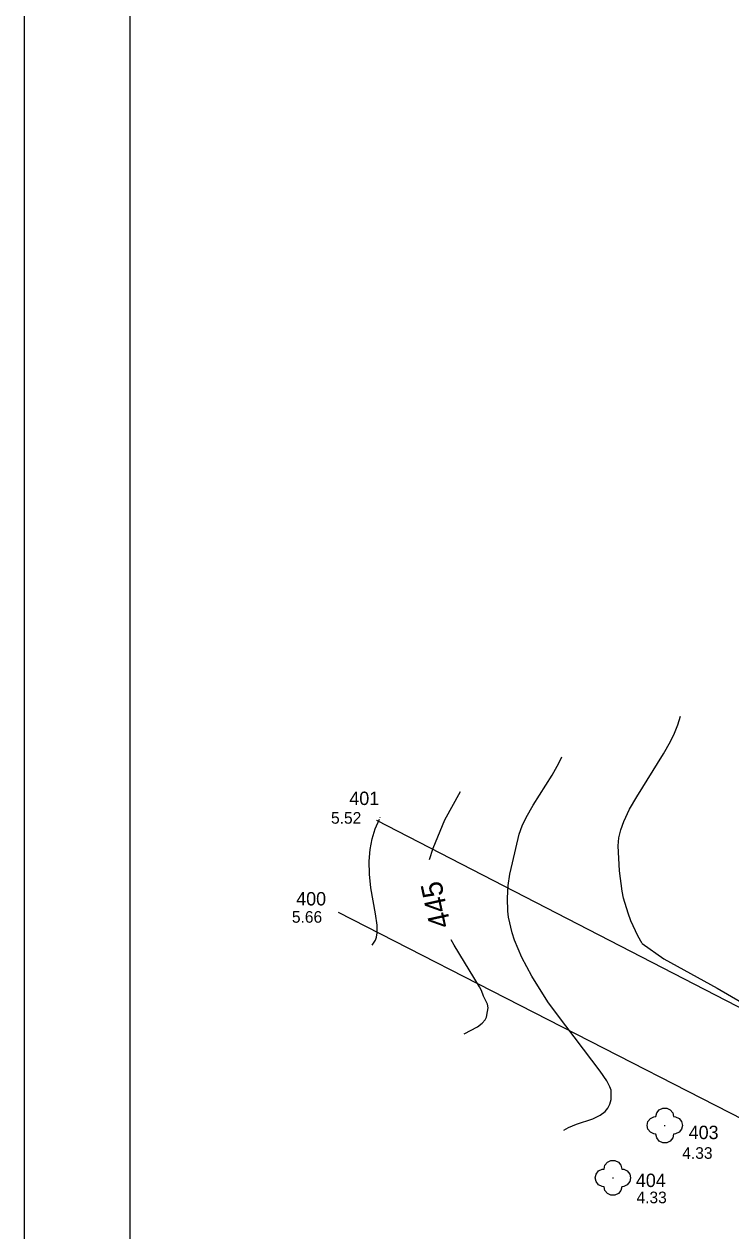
# Model space of a CAD drawing. Extents: x -792549 to -792339, y -1111914 to -1111617.
# Drawn here: x -792548.56 to -792528.5, y -1111704.34 to -1111670.1 of the extents above; entities that cross this region are included whole.
import ezdxf

# ---------------------------------------------------------------- set-up
doc = ezdxf.new("R2010")
doc.units = 0
for name, color, linetype in [('Vrstva 1', 7, 'Continuous'), ('Vrstva 24', 7, 'Continuous'), ('Vrstva 31', 7, 'Continuous'), ('Vrstva 32', 7, 'Continuous'), ('Vrstva 33', 7, 'Continuous'), ('Vrstva 44', 7, 'Continuous'), ('Vrstva 47', 7, 'Continuous'), ('Vrstva 48', 7, 'Continuous'), ('Vrstva 49', 7, 'Continuous'), ('Vrstva 50', 7, 'Continuous'), ('Vrstva 60', 7, 'Continuous')]:
    doc.layers.add(name, color=color, linetype=linetype)

# ---------------------------------------------------------------- blocks, each defined once
blk = doc.blocks.new('SC6231')
at = {"layer": 'Vrstva 1'}
blk.add_line((0, 0), (0, 0), dxfattribs=at)
blk = doc.blocks.new('3$1300')
at = {"layer": 'Vrstva 1'}
for points in [[(20, 0), (19, -4.3), (16.2, -7.8), (12.2, -9.7), (10, -10), (9, -14.3), (6.2, -17.8), (2.2, -19.7), (-2.3, -19.7), (-6.3, -17.8), (-9.1, -14.3), (-10.1, -10), (-12.3, -9.7), (-16.3, -7.8), (-19.1, -4.3), (-20.1, 0), (-19.1, 4.3), (-16.3, 7.8), (-12.3, 9.7), (-10.1, 10), (-9.1, 14.3), (-6.3, 17.8), (-2.3, 19.7), (2.2, 19.7), (6.2, 17.8), (9, 14.3), (10, 10), (12.2, 9.7), (16.2, 7.8), (19, 4.3), (20, 0)], [(-0.5, 0), (0, 0), (0.5, 0)]]:
    blk.add_lwpolyline(points, dxfattribs=at)

msp = doc.modelspace()

# ---------------------------------------------------------------- linework, layer by layer
at = {"layer": 'Vrstva 24'}
msp.add_lwpolyline([(-792545.564, -1111620.164), (-792545.564, -1111911.164), (-792341.564, -1111911.164), (-792341.564, -1111620.164)], close=True, dxfattribs=at)
at = {"layer": 'Vrstva 31'}
for points in [[(-792537.054, -1111693.81), (-792536.956, -1111693.489), (-792536.619, -1111692.678), (-792536.174, -1111691.875)], [(-792535.584, -1111697.527), (-792535.641, -1111697.417), (-792536.356, -1111696.239), (-792536.44, -1111696.085)], [(-792535.436, -1111698.281), (-792535.408, -1111698.115), (-792535.391, -1111698.015), (-792535.414, -1111697.915), (-792535.47, -1111697.8), (-792535.526, -1111697.684), (-792535.584, -1111697.527)], [(-792536.078, -1111698.754), (-792535.696, -1111698.556), (-792535.559, -1111698.452), (-792535.478, -1111698.357), (-792535.436, -1111698.281)]]:
    msp.add_lwpolyline(points, dxfattribs=at)
at = {"layer": 'Vrstva 32'}
for points in [[(-792531.018, -1111696.194), (-792531.146, -1111695.973), (-792531.343, -1111695.543), (-792531.423, -1111695.333), (-792531.547, -1111694.902), (-792531.59, -1111694.704), (-792531.667, -1111694.129), (-792531.704, -1111693.421), (-792531.686, -1111693.195), (-792531.631, -1111692.964), (-792531.544, -1111692.728), (-792531.377, -1111692.38), (-792531.175, -1111692.031), (-792530.412, -1111690.809), (-792530.219, -1111690.46), (-792530.103, -1111690.221), (-792530.006, -1111689.985), (-792529.931, -1111689.743)], [(-792531.018, -1111696.194), (-792530.405, -1111696.621), (-792528.894, -1111697.453), (-792527.31, -1111698.376), (-792527.094, -1111698.351), (-792526.964, -1111698.246)]]:
    msp.add_lwpolyline(points, dxfattribs=at)
at = {"layer": 'Vrstva 33'}
for points in [[(-792533.246, -1111701.491), (-792533.116, -1111701.408), (-792532.89, -1111701.318), (-792532.421, -1111701.163), (-792532.213, -1111701.061), (-792532.076, -1111700.958), (-792531.994, -1111700.863), (-792531.935, -1111700.752), (-792531.899, -1111700.617), (-792531.897, -1111700.388), (-792531.904, -1111700.347), (-792531.938, -1111700.258), (-792532.026, -1111700.089), (-792532.213, -1111699.812), (-792533.429, -1111698.216), (-792533.698, -1111697.844), (-792534.154, -1111697.114), (-792534.441, -1111696.588), (-792534.641, -1111696.098), (-792534.716, -1111695.883), (-792534.811, -1111695.44), (-792534.839, -1111695.27), (-792534.848, -1111694.899), (-792534.822, -1111694.541), (-792534.774, -1111694.221), (-792534.705, -1111693.898), (-792534.511, -1111693.089), (-792534.432, -1111692.854), (-792534.318, -1111692.614), (-792534.114, -1111692.262), (-792533.574, -1111691.414), (-792533.384, -1111691.069), (-792533.301, -1111690.894)], [(-792538.685, -1111696.233), (-792538.59, -1111696.092), (-792538.56, -1111696.008), (-792538.541, -1111695.883), (-792538.547, -1111695.67), (-792538.592, -1111695.348), (-792538.719, -1111694.606), (-792538.76, -1111694.221), (-792538.768, -1111693.855), (-792538.743, -1111693.525), (-792538.685, -1111693.219), (-792538.599, -1111692.94), (-792538.476, -1111692.661)], [(-792538.46, -1111692.624), (-792538.455, -1111692.614)]]:
    msp.add_lwpolyline(points, dxfattribs=at)
at = {"layer": 'Vrstva 47'}
for p, q in [((-792538.56, -1111692.69), (-792525.74, -1111699.3)), ((-792527.11, -1111701.73), (-792539.64, -1111695.31))]:
    msp.add_line(p, q, dxfattribs=at)
at = {"layer": 'Vrstva 60'}
msp.add_lwpolyline([(-792548.564, -1111617.164), (-792548.564, -1111914.164), (-792338.564, -1111914.164), (-792338.564, -1111617.164), (-792548.564, -1111617.164)], dxfattribs=at)

# ---------------------------------------------------------------- block references
at = {"layer": 'Vrstva 44', "xscale": 0.025, "yscale": 0.025000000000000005}
for p in [(-792530.38, -1111701.35), (-792531.85, -1111702.84)]:
    msp.add_blockref('3$1300', p, dxfattribs=at)
at = {"layer": 'Vrstva 48', "xscale": 0.1, "yscale": 0.10000000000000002}
for p in [(-792538.56, -1111692.69), (-792539.64, -1111695.31), (-792530.38, -1111701.35), (-792531.85, -1111702.84)]:
    msp.add_blockref('SC6231', p, dxfattribs=at)

# ---------------------------------------------------------------- texts
at = {"layer": 'Vrstva 31'}
msp.add_text('445', height=0.6, rotation=102.3983, dxfattribs=at).set_placement((-792536.448, -1111695.688))
at = {"layer": 'Vrstva 49'}
for s, p in [('401', (-792539.333, -1111692.26)), ('400', (-792540.841, -1111695.11)), ('403', (-792529.701, -1111701.74)), ('404', (-792531.2, -1111703.1))]:
    msp.add_text(s, height=0.38, dxfattribs=at).set_placement(p)
at = {"layer": 'Vrstva 50'}
for s, p in [('5.52', (-792539.853, -1111692.79)), ('5.66', (-792540.963, -1111695.6)), ('4.33', (-792529.883, -1111702.3)), ('4.33', (-792531.183, -1111703.56))]:
    msp.add_text(s, height=0.33, dxfattribs=at).set_placement(p)

doc.saveas('drawing.dxf')
